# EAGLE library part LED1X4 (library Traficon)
4 leds in one package
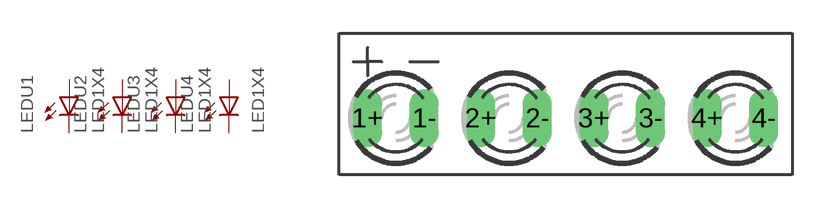
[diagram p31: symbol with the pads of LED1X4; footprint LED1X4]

Designator prefix LED; gates U1=LED U2=LED U3=LED U4=LED

## LED1X4  [LED1X4]
1+  U1:A  pas
1-  U1:C  pas
2+  U2:A  pas
2-  U2:C  pas
3+  U3:A  pas
3-  U3:C  pas
4+  U4:A  pas
4-  U4:C  pas

## Footprint LED1X4 (pad centres in mm)
drill 0.8 long: 1+ -7.62,0; 1- -5.08,0; 2+ -2.54,0; 2- 0,0; 3+ 2.54,0; 3- 5.08,0; 4+ 7.62,0; 4- 10.16,0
